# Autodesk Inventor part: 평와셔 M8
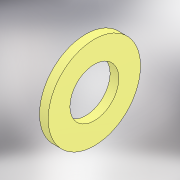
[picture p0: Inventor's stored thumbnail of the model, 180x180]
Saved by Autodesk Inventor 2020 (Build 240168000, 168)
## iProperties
Created: 2024-11
Part Number: 평와셔 M8
Material: 강철, 연강
Description: 평면 와셔
Document SubType Name: Modeling
Designer: 1강의실14
Density: 7.85 g/cm^3
Appearance: 기본값
Author: jhkim
Sending System: Autodesk Inventor 2025
Preprocessor: ST-DEVELOPER v20
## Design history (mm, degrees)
feature "Solid1"
node "솔리드1"
